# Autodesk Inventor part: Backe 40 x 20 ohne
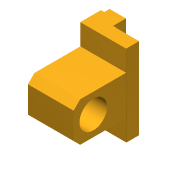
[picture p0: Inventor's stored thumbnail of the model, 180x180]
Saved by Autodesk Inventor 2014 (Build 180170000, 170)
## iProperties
Created: 2014-03
Part Number: Backe 40 x 20 ohne
Material: Generisch
Document SubType Name: Modeling
Designer: e_dammj
Density: 1 g/cm^3
Appearance: Vorgabe
Sending System: SolidWorks 2011
Last Author: e_boekem
Author: e_dammj
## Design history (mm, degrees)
node "Backe 40 x 20 ohne.ipt1"
node "Fase11"
node "Aufsatz-Linear austragen5"
node "Basis1"
node "Basis2"
